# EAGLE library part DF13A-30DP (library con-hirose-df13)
DF13-30DP Double row, 1.25mm Pitch Miniature Crimping Connector.
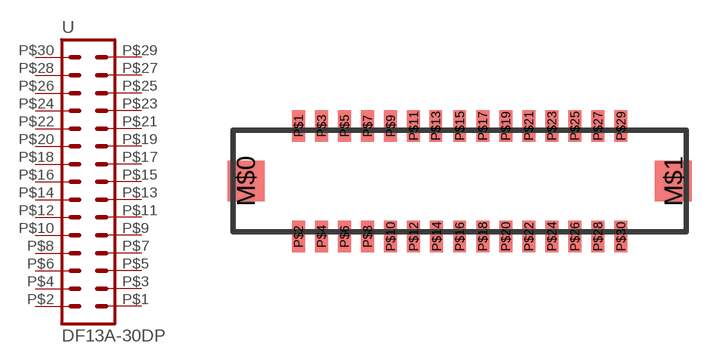
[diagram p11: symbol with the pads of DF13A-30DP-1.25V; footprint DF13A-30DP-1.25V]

Designator prefix -

## DF13A-30DP40DP-1.25V  [DF13A-30DP-1.25V]
P$1  1  pas
P$2  2  pas
P$3  3  pas
P$4  4  pas
P$5  5  pas
P$6  6  pas
P$7  7  pas
P$8  8  pas
P$9  9  pas
P$10  10  pas
P$11  11  pas
P$12  12  pas
P$13  13  pas
P$14  14  pas
P$15  15  pas
P$16  16  pas
P$17  17  pas
P$18  18  pas
P$19  19  pas
P$20  20  pas
P$21  21  pas
P$22  22  pas
P$23  23  pas
P$24  24  pas
P$25  25  pas
P$26  26  pas
P$27  27  pas
P$28  28  pas
P$29  29  pas
P$30  30  pas

## Footprint DF13A-30DP-1.25V (pad centres in mm)
Double Row Straight Pin Header (SMT)
smd 2 x 2.2: M$0 -11.6,0; M$1 11.6,0
smd 0.7 x 1.7: P$1 -8.75,3; P$2 -8.75,-3; P$3 -7.5,3; P$4 -7.5,-3; P$5 -6.25,3; P$6 -6.25,-3; P$7 -5,3; P$8 -5,-3; P$9 -3.75,3; P$10 -3.75,-3; P$11 -2.5,3; P$12 -2.5,-3; P$13 -1.3,3; P$14 -1.25,-3; P$15 0,3; P$16 0,-3; P$17 1.25,3; P$18 1.25,-3; P$19 2.5,3; P$20 2.5,-3; P$21 3.75,3; P$22 3.75,-3; P$23 5,3; P$24 5,-3; P$25 6.25,3; P$26 6.25,-3; P$27 7.5,3; P$28 7.5,-3; P$29 8.75,3; P$30 8.75,-3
